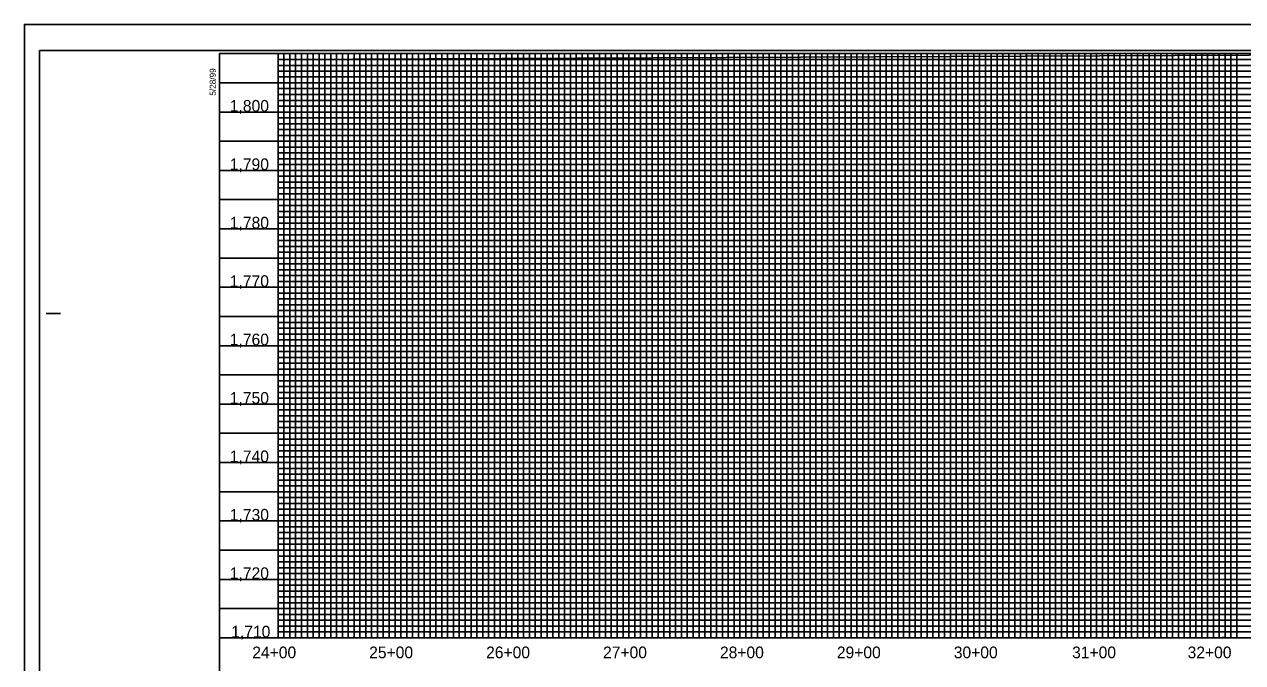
# Model space of a CAD drawing. Extents: x 497599 to 513368, y 404140 to 476034.
# Drawn here: x 505692 to 506734, y 439315 to 439861 of the extents above; entities that cross this region are included whole.
import ezdxf

# ---------------------------------------------------------------- set-up
doc = ezdxf.new("R2010")
doc.units = 0
for name, color, linetype in [('Exist Vertical Profile Vertical Axis Label', 7, 'Continuous'), ('Sheet Cutting Line CELL', 7, 'Continuous'), ('Sheet DOT Grid CELL', 7, 'Continuous'), ('Sheet Layout Profile Border Port 1', 7, 'Continuous'), ('Sheet Plot Border Inside CELL', 7, 'Continuous'), ('Sheet Plot Border Outside CELL', 7, 'Continuous'), ('Sheet Profile CELL', 7, 'Continuous'), ('Sheet Profile Grid Major CELL', 7, 'Continuous'), ('Sheet Profile Grid Middle CELL', 7, 'Continuous'), ('Sheet Profile Grid Minor CELL', 7, 'Continuous')]:
    doc.layers.add(name, color=color, linetype=linetype)

msp = doc.modelspace()

# ---------------------------------------------------------------- linework, layer by layer
at = {"layer": 'Sheet Cutting Line CELL'}
for p, q in [((507375.7, 439861.1), (505691.7, 439861.1)), ((505691.7, 439861.1), (505691.7, 438761.1))]:
    msp.add_line(p, q, dxfattribs=at)
at = {"layer": 'Sheet DOT Grid CELL'}
for p, q in [((505908.7, 439336.1), (505908.7, 439836.1)), ((505958.7, 439336.1), (505958.7, 439836.1)), ((506008.7, 439336.1), (506008.7, 439836.1)), ((506058.7, 439336.1), (506058.7, 439836.1)), ((506108.7, 439336.1), (506108.7, 439836.1)), ((506158.7, 439336.1), (506158.7, 439836.1)), ((506208.7, 439336.1), (506208.7, 439836.1)), ((506258.7, 439336.1), (506258.7, 439836.1)), ((506308.7, 439336.1), (506308.7, 439836.1)), ((506358.7, 439336.1), (506358.7, 439836.1)), ((506408.7, 439336.1), (506408.7, 439836.1)), ((506458.7, 439336.1), (506458.7, 439836.1)), ((506508.7, 439336.1), (506508.7, 439836.1)), ((506558.7, 439336.1), (506558.7, 439836.1)), ((506608.7, 439336.1), (506608.7, 439836.1)), ((506658.7, 439336.1), (506658.7, 439836.1)), ((506708.7, 439336.1), (506708.7, 439836.1)), ((507158.6, 439786.1), (505858.7, 439786.1)), ((507158.6, 439736.1), (505858.7, 439736.1)), ((507158.7, 439686.1), (505858.7, 439686.1)), ((507358.7, 439636.1), (505858.7, 439636.1)), ((507358.7, 439586.1), (505858.7, 439586.1)), ((507358.7, 439536.1), (505858.7, 439536.1)), ((507358.7, 439486.1), (505858.7, 439486.1)), ((507358.7, 439436.1), (505858.7, 439436.1)), ((507358.7, 439386.1), (505858.7, 439386.1))]:
    msp.add_line(p, q, dxfattribs=at)
at = {"layer": 'Sheet Layout Profile Border Port 1'}
msp.add_lwpolyline([(505908.7, 439831.1), (507058.7, 439836.1), (507108.7, 439836.1), (507108.7, 439786.1), (507108.7, 439336.1), (505908.7, 439336.1)], close=True, dxfattribs=at)
at = {"layer": 'Sheet Plot Border Inside CELL'}
msp.add_lwpolyline([(505704.7, 438783.6), (507371.2, 438783.6), (507371.2, 439838.7), (505704.7, 439838.7)], close=True, dxfattribs=at)
at = {"layer": 'Sheet Plot Border Outside CELL'}
msp.add_lwpolyline([(505691.7, 438761.1), (507375.7, 438761.1), (507375.7, 439861.1), (505691.7, 439861.1)], close=True, dxfattribs=at)
at = {"layer": 'Sheet Profile CELL'}
for p, q in [((505710.2, 439613.6), (505722.7, 439613.6)), ((505858.7, 439336.1), (507358.7, 439336.1))]:
    msp.add_line(p, q, dxfattribs=at)
msp.add_lwpolyline([(507358.7, 439836.1), (505858.7, 439836.1), (505858.7, 438786.1), (507358.7, 438786.1)], close=True, dxfattribs=at)
at = {"layer": 'Sheet Profile Grid Major CELL'}
for points in [[(505908.7, 439836.1), (505908.7, 439336.1), (505958.7, 439336.1), (505958.7, 439836.1), (506008.7, 439836.1), (506008.7, 439336.1), (506058.7, 439336.1), (506058.7, 439836.1), (506108.7, 439836.1), (506108.7, 439336.1), (506158.7, 439336.1), (506158.7, 439836.1), (506208.7, 439836.1), (506208.7, 439336.1), (506258.7, 439336.1), (506258.7, 439836.1), (506308.7, 439836.1), (506308.7, 439336.1), (506358.7, 439336.1), (506358.7, 439836.1), (506408.7, 439836.1), (506408.7, 439336.1), (506458.7, 439336.1), (506458.7, 439836.1), (506508.7, 439836.1), (506508.7, 439336.1), (506558.7, 439336.1), (506558.7, 439836.1), (506608.7, 439836.1), (506608.7, 439336.1), (506658.7, 439336.1), (506658.7, 439836.1), (506708.7, 439836.1), (506708.7, 439336.1), (506758.7, 439336.1)], [(505858.7, 439786.1), (507158.7, 439786.1)], [(507158.7, 439736.1), (505858.7, 439736.1), (505858.7, 439686.1), (507158.7, 439686.1)], [(507358.7, 439636.1), (505858.7, 439636.1), (505858.7, 439586.1), (507358.7, 439586.1)], [(507358.7, 439536.1), (505858.7, 439536.1), (505858.7, 439486.1), (507358.7, 439486.1)], [(507358.7, 439436.1), (505858.7, 439436.1), (505858.7, 439436.1), (505858.7, 439386.1), (507358.7, 439386.1)]]:
    msp.add_lwpolyline(points, dxfattribs=at)
at = {"layer": 'Sheet Profile Grid Middle CELL'}
msp.add_line((505858.7, 439811.1), (507158.6, 439811.1), dxfattribs=at)
for points in [[(505933.7, 439836.1), (505933.7, 439336.1), (505983.7, 439336.1), (505983.7, 439836.1), (506033.7, 439836.1), (506033.7, 439336.1), (506083.7, 439336.1), (506083.7, 439836.1), (506133.7, 439836.1), (506133.7, 439336.1), (506183.7, 439336.1), (506183.7, 439836.1), (506233.7, 439836.1), (506233.7, 439336.1), (506283.7, 439336.1), (506283.7, 439836.1), (506333.7, 439836.1), (506333.7, 439336.1), (506383.7, 439336.1), (506383.7, 439836.1), (506433.7, 439836.1), (506433.7, 439336.1), (506483.7, 439336.1), (506483.7, 439336.1), (506483.7, 439836.1), (506533.7, 439836.1), (506533.7, 439336.1), (506583.7, 439336.1), (506583.7, 439836.1), (506633.7, 439836.1), (506633.7, 439336.1), (506683.7, 439336.1), (506683.7, 439836.1), (506733.7, 439836.1)], [(507158.7, 439761.1), (505858.7, 439761.1), (505858.7, 439711.1), (507158.7, 439711.1)], [(507358.7, 439661.1), (505858.7, 439661.1), (505858.7, 439611.1), (507183.7, 439611.1)], [(507358.7, 439561.1), (505858.7, 439561.1), (505858.7, 439511.1), (507358.7, 439511.1)], [(507358.7, 439461.1), (505858.7, 439461.1), (505858.7, 439411.1), (507358.7, 439411.1)], [(507358.7, 439361.1), (505858.7, 439361.1)]]:
    msp.add_lwpolyline(points, dxfattribs=at)
at = {"layer": 'Sheet Profile Grid Minor CELL'}
for p, q in [((505908.7, 439831.1), (507158.7, 439831.1)), ((505908.7, 439826.1), (505908.7, 439826.1)), ((507158.7, 439826.1), (505908.7, 439825.8)), ((505908.7, 439821.1), (507158.7, 439821.1)), ((507158.6, 439701.1), (505908.7, 439701.1)), ((507158.7, 439696.1), (505908.7, 439696.1)), ((507158.7, 439691.1), (505908.7, 439691.1)), ((505908.7, 439681.1), (507158.7, 439681.1)), ((507158.7, 439676.1), (505908.7, 439676.1)), ((505908.7, 439671.1), (507308.7, 439671.1)), ((507308.7, 439651.1), (505908.7, 439651.1)), ((505908.7, 439646.1), (507308.7, 439646.1)), ((507308.7, 439626.1), (505908.7, 439626.1)), ((505908.7, 439621.1), (507308.7, 439621.1)), ((507308.7, 439601.1), (505908.7, 439601.1)), ((505908.7, 439596.1), (507308.7, 439596.1)), ((507308.7, 439591.1), (505908.7, 439591.1)), ((505908.7, 439581.1), (507308.7, 439581.1)), ((507308.7, 439576.1), (505908.7, 439576.1)), ((505908.7, 439571.1), (507308.7, 439571.1)), ((507308.7, 439566.1), (505908.7, 439566.1)), ((505908.7, 439556.1), (507308.7, 439556.1)), ((507308.7, 439551.1), (505908.7, 439551.1)), ((505908.7, 439546.1), (507308.7, 439546.1)), ((507308.7, 439541.1), (505908.7, 439541.1)), ((505908.7, 439531.1), (507308.7, 439531.1)), ((507308.7, 439526.1), (505908.7, 439526.1)), ((505908.7, 439521.1), (507308.7, 439521.1)), ((507308.7, 439516.1), (505908.7, 439516.1)), ((505908.7, 439506.1), (507308.7, 439506.1)), ((507308.7, 439501.1), (505908.7, 439501.1)), ((505908.7, 439496.1), (507308.7, 439496.1)), ((507308.7, 439491.1), (505908.7, 439491.1)), ((505908.7, 439481.1), (507308.7, 439481.1)), ((507308.7, 439476.1), (505908.7, 439476.1)), ((505908.7, 439471.1), (507308.7, 439471.1)), ((507308.7, 439466.1), (505908.7, 439466.1)), ((505908.7, 439456.1), (507308.7, 439456.1)), ((507308.7, 439451.1), (505908.7, 439451.1)), ((507308.7, 439446.1), (505908.7, 439446.1)), ((507308.7, 439441.1), (505908.7, 439441.1)), ((505908.7, 439431.1), (507308.7, 439431.1)), ((507308.7, 439426.1), (505908.7, 439426.1)), ((505908.7, 439421.1), (507308.7, 439421.1)), ((507308.7, 439416.1), (505908.7, 439416.1)), ((505908.7, 439406.1), (507308.7, 439406.1)), ((507308.7, 439401.1), (505908.7, 439401.1)), ((505908.7, 439396.1), (507308.7, 439396.1)), ((507308.7, 439391.1), (505908.7, 439391.1)), ((505908.7, 439381.1), (507308.7, 439381.1)), ((507308.7, 439376.1), (505908.7, 439376.1)), ((505908.7, 439371.1), (507308.7, 439371.1)), ((507308.7, 439366.1), (505908.7, 439366.1)), ((505908.7, 439356.1), (507308.7, 439356.1)), ((507308.7, 439351.1), (505908.7, 439351.1)), ((505908.7, 439346.1), (507308.7, 439346.1))]:
    msp.add_line(p, q, dxfattribs=at)
for points in [[(505913.7, 439836.1), (505913.7, 439336.1), (505918.7, 439336.1), (505918.7, 439836.1), (505923.7, 439836.1), (505923.7, 439336.1), (505928.7, 439336.1), (505928.7, 439836.1), (505938.7, 439836.1), (505938.7, 439336.1), (505943.7, 439336.1), (505943.7, 439836.1), (505948.7, 439836.1), (505948.7, 439336.1), (505953.7, 439336.1), (505963.7, 439336.1), (505968.7, 439336.1), (505968.7, 439836.1), (505973.7, 439836.1), (505973.7, 439336.1), (505978.7, 439336.1), (505978.7, 439836.1), (505988.7, 439836.1), (505988.7, 439336.1), (505993.7, 439336.1), (505993.7, 439836.1), (505998.7, 439836.1), (505998.7, 439336.1), (506003.7, 439336.1), (506003.7, 439836.1), (506013.7, 439836.1), (506013.7, 439336.1), (506018.7, 439336.1), (506018.7, 439836.1), (506023.7, 439836.1), (506023.7, 439336.1), (506028.7, 439336.1), (506028.7, 439836.1), (506038.7, 439836.1), (506038.7, 439336.1), (506043.7, 439336.1), (506043.7, 439836.1), (506048.7, 439836.1), (506048.7, 439336.1), (506053.7, 439336.1), (506053.7, 439836.1), (506063.7, 439836.1), (506063.7, 439336.1), (506068.7, 439336.1), (506068.7, 439836.1), (506073.7, 439836.1), (506073.7, 439336.1), (506078.7, 439336.1), (506078.7, 439836.1), (506088.7, 439836.1), (506088.7, 439336.1), (506093.7, 439336.1), (506093.7, 439836.1), (506098.7, 439836.1), (506098.7, 439336.1), (506103.7, 439336.1), (506103.7, 439836.1), (506113.7, 439836.1), (506113.7, 439336.1), (506118.7, 439336.1), (506118.7, 439836.1), (506123.7, 439836.1), (506123.7, 439336.1)], [(505953.7, 439336.1), (505953.7, 439836.1), (505963.7, 439836.1), (505963.7, 439336.1)], [(506123.7, 439336.1), (506128.7, 439336.1), (506128.7, 439836.1), (506138.7, 439836.1), (506138.7, 439336.1), (506143.7, 439336.1), (506143.7, 439836.1), (506148.7, 439836.1), (506148.7, 439336.1), (506153.7, 439336.1), (506153.7, 439836.1), (506163.7, 439836.1), (506163.7, 439336.1), (506168.7, 439336.1), (506168.7, 439836.1), (506173.7, 439836.1), (506173.7, 439336.1), (506178.7, 439336.1), (506178.7, 439836.1), (506188.7, 439836.1), (506188.7, 439336.1), (506193.7, 439336.1), (506193.7, 439836.1), (506198.7, 439836.1), (506198.7, 439336.1), (506203.7, 439336.1), (506203.7, 439836.1), (506213.7, 439836.1), (506213.7, 439336.1), (506218.7, 439336.1), (506218.7, 439836.1), (506223.7, 439836.1), (506223.7, 439336.1), (506228.7, 439336.1), (506228.7, 439836.1), (506238.7, 439836.1), (506238.7, 439336.1), (506243.7, 439336.1), (506243.7, 439836.1), (506248.7, 439836.1), (506248.7, 439336.1), (506253.7, 439336.1), (506253.7, 439836.1), (506263.7, 439836.1), (506263.7, 439336.1), (506268.7, 439336.1), (506268.7, 439836.1), (506273.7, 439836.1), (506273.7, 439336.1), (506278.7, 439336.1), (506278.7, 439836.1), (506288.7, 439836.1), (506288.7, 439336.1), (506293.7, 439336.1), (506293.7, 439836.1), (506298.7, 439836.1), (506298.7, 439336.1), (506303.7, 439336.1), (506303.7, 439836.1), (506313.7, 439836.1), (506313.7, 439336.1), (506318.7, 439336.1), (506318.7, 439836.1), (506323.7, 439836.1), (506323.7, 439336.1), (506328.7, 439336.1), (506328.7, 439836.1), (506338.7, 439836.1), (506338.7, 439336.1), (506343.7, 439336.1), (506343.7, 439836.1), (506348.7, 439836.1), (506348.7, 439336.1), (506353.7, 439336.1), (506353.7, 439836.1), (506363.7, 439836.1), (506363.7, 439336.1), (506368.7, 439336.1), (506368.7, 439836.1), (506373.7, 439836.1), (506373.7, 439336.1), (506378.7, 439336.1), (506378.7, 439836.1), (506388.7, 439836.1), (506388.7, 439336.1), (506393.7, 439336.1), (506393.7, 439836.1), (506398.7, 439836.1), (506398.7, 439336.1), (506403.7, 439336.1), (506403.7, 439836.1), (506413.7, 439836.1), (506413.7, 439336.1), (506418.7, 439336.1), (506418.7, 439836.1), (506423.7, 439836.1), (506423.7, 439336.1), (506428.7, 439336.1), (506428.7, 439836.1), (506438.7, 439836.1)], [(506438.7, 439836.1), (506438.7, 439336.1), (506443.7, 439336.1), (506443.7, 439836.1), (506448.7, 439836.1), (506448.7, 439336.1), (506453.7, 439336.1), (506453.7, 439836.1), (506463.7, 439836.1), (506463.7, 439336.1), (506468.7, 439336.1), (506468.7, 439836.1), (506473.7, 439836.1), (506473.7, 439336.1), (506478.7, 439336.1), (506478.7, 439836.1), (506488.7, 439836.1), (506488.7, 439336.1), (506493.7, 439336.1), (506493.7, 439836.1), (506498.7, 439836.1), (506498.7, 439336.1), (506503.7, 439336.1), (506503.7, 439836.1), (506513.7, 439836.1), (506513.7, 439336.1), (506518.7, 439336.1), (506518.7, 439836.1), (506523.7, 439836.1), (506523.7, 439336.1), (506528.7, 439336.1), (506528.7, 439836.1), (506538.7, 439836.1), (506538.7, 439336.1), (506543.7, 439336.1), (506543.7, 439836.1), (506548.7, 439836.1), (506548.7, 439336.1), (506553.7, 439336.1), (506553.7, 439836.1), (506563.7, 439836.1), (506563.7, 439336.1), (506563.7, 439336.1), (506568.7, 439336.1), (506568.7, 439836.1), (506573.7, 439836.1), (506573.7, 439336.1), (506578.7, 439336.1), (506578.7, 439836.1), (506588.7, 439836.1), (506588.7, 439336.1), (506593.7, 439336.1), (506593.7, 439836.1), (506598.7, 439836.1), (506598.7, 439336.1), (506603.7, 439336.1), (506603.7, 439836.1), (506613.7, 439836.1), (506613.7, 439336.1), (506618.7, 439336.1), (506618.7, 439836.1), (506623.7, 439836.1), (506623.7, 439336.1), (506628.7, 439336.1), (506628.7, 439836.1), (506638.7, 439836.1), (506638.7, 439336.1), (506643.7, 439336.1), (506643.7, 439836.1), (506648.7, 439836.1), (506648.7, 439336.1), (506653.7, 439336.1), (506653.7, 439836.1), (506663.7, 439836.1), (506663.7, 439336.1), (506668.7, 439336.1), (506668.7, 439836.1), (506673.7, 439836.1), (506673.7, 439336.1), (506678.7, 439336.1), (506678.7, 439836.1), (506688.7, 439836.1), (506688.7, 439336.1), (506693.7, 439336.1), (506693.7, 439836.1), (506698.7, 439836.1), (506698.7, 439336.1), (506703.7, 439336.1), (506703.7, 439836.1), (506713.7, 439836.1), (506713.7, 439336.1), (506718.4, 439336.7), (506718.7, 439336.1), (506718.7, 439836.1), (506723.7, 439836.1), (506723.7, 439336.1), (506728.7, 439336.1), (506728.7, 439836.1), (506738.7, 439836.1)], [(507158.7, 439816.1), (505908.7, 439816.1), (505908.7, 439806.1), (507158.7, 439806.1)], [(507158.6, 439801.1), (505908.7, 439801.1), (505908.7, 439796.1), (507158.7, 439796.1)], [(507158.7, 439791.1), (505908.7, 439791.1), (505908.7, 439781.1), (507158.7, 439781.1)], [(507158.7, 439776.1), (505908.7, 439776.1), (505908.7, 439771.1), (507158.7, 439771.1)], [(507158.7, 439766.1), (505908.7, 439766.1), (505908.7, 439756.1), (507158.7, 439756.1)], [(507158.7, 439751.1), (505908.7, 439751.1), (505908.7, 439746.1), (507158.7, 439746.1)], [(507158.7, 439741.1), (505908.7, 439741.1), (505908.7, 439731.1), (507158.7, 439731.1)], [(507158.7, 439726), (505908.8, 439726), (505908.8, 439721.1), (507158.7, 439721.1)], [(507158.7, 439716.1), (505908.7, 439716.1), (505908.7, 439706.1), (507158.7, 439706.1)], [(507308.7, 439666.1), (505908.7, 439666.1), (505908.7, 439656.1), (507308.7, 439656.1)], [(507308.7, 439641.1), (505908.7, 439641.1), (505908.7, 439631.1), (507308.7, 439631.1)], [(507308.7, 439616.1), (505908.7, 439616.1), (505908.7, 439606.1), (507308.7, 439606.1)], [(507308.7, 439341.1), (505908.7, 439341.1)]]:
    msp.add_lwpolyline(points, dxfattribs=at)

# ---------------------------------------------------------------- texts
at = {"layer": 'Exist Vertical Profile Vertical Axis Label'}
for s, p in [('1,800', (505867.4, 439786.4)), ('1,790', (505867.4, 439736.4)), ('1,780', (505867.4, 439686.4)), ('1,770', (505867.4, 439636.4)), ('1,760', (505867.4, 439586.4)), ('1,750', (505867.4, 439536.4)), ('1,740', (505867.4, 439486.4)), ('1,730', (505867.4, 439436.4)), ('1,720', (505867.4, 439386.4)), ('1,710', (505868.6, 439336.4)), ('24+00', (505886.6, 439318.6)), ('25+00', (505986.6, 439318.6)), ('26+00', (506086.6, 439318.6)), ('27+00', (506186.6, 439318.6)), ('28+00', (506286.6, 439318.6)), ('29+00', (506386.6, 439318.6)), ('30+00', (506486.6, 439318.6)), ('31+00', (506587.8, 439318.6)), ('32+00', (506686.6, 439318.6))]:
    msp.add_text(s, height=10, dxfattribs=at).set_placement(p)
at = {"layer": 'Sheet Profile CELL'}
msp.add_text('5/28/99', height=5.25, rotation=90, dxfattribs=at).set_placement((505855.4, 439800.1))

doc.saveas('drawing.dxf')
